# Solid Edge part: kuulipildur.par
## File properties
Author: Georg
Template: Iso Metric Part.par
Last saved by: Georg
Revision: 2
Application: Solid Edge
Accuracy: 0,990
Face Style: Model Default
Fill Style: Normal
Coef. of Thermal Exp: 0.0
Thermal Conductivity: 0.0
Specific Heat: 0.0
Modulus of Elasticity: 0.0
Poisson's Ratio: 0.0
Yield Stress: 0.0
Ultimate Stress: 0.0
Elongation: 0.0
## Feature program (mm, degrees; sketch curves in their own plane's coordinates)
sketch for "ExtrudedProtrusion_1" plane through (0, 4000, -150) normal (0, 0, 1) x-axis (1, 0, 0)
  circle centre (0, 420.2777) radius 100
extrude "ExtrudedProtrusion_1" add finite 20 along -normal
sketch for "ExtrudedProtrusion_6" plane through (0, 4350.2777, -620) normal (0, -1, 0) x-axis (1, 0, 0)
  circle centre (0, 0) radius 15
extrude "ExtrudedProtrusion_6" add finite 10 along +normal
sketch for "ExtrudedProtrusion_7" plane through (0, 4340.2777, -620) normal (0, -1, 0) x-axis (1, 0, 0)
  circle centre (0, 0) radius 100
extrude "ExtrudedProtrusion_7" add finite 20 along +normal
sketch for "ExtrudedProtrusion_8" plane through (0, 4320.2777, -620) normal (0, -1, 0) x-axis (1, 0, 0)
  circle centre (0, 59.2762) radius 30
extrude "ExtrudedProtrusion_8" add finite 520 along +normal
sketch for "ExtrudedProtrusion_9" #1 plane through (0, 3800.2777, -560.7238) normal (0, -1, 0) x-axis (1, 0, 0)
  circle centre (0, 0) radius 25
sketch for "ExtrudedProtrusion_9" #2 plane through (0, 3800.2777, -560.7238) normal (0, -1, 0) x-axis (1, 0, 0)
  circle centre (0, 0) radius 30
extrude "ExtrudedProtrusion_9" add finite 10 along +normal
sketch for "ExtrudedCutout_3" plane through (0, 3800.2777, -560.7238) normal (0, -1, 0) x-axis (1, 0, 0)
  circle centre (0, 0) radius 20
extrude "ExtrudedCutout_3" cut finite 510 along -normal
sketch for "ExtrudedCutout_4" #1 plane through (37.5, 4420.2777, -420) normal (-1, 0, 0) x-axis (0, 0, -1)
  circle centre (140.7238, 540) radius 12.5
sketch for "ExtrudedCutout_4" #2 plane through (37.5, 4420.2777, -420) normal (-1, 0, 0) x-axis (0, 0, -1)
  circle centre (140.7238, 480) radius 12.5
sketch for "ExtrudedCutout_4" #3 plane through (37.5, 4420.2777, -420) normal (-1, 0, 0) x-axis (0, 0, -1)
  circle centre (140.7238, 420) radius 12.5
sketch for "ExtrudedCutout_4" #4 plane through (37.5, 4420.2777, -420) normal (-1, 0, 0) x-axis (0, 0, -1)
  circle centre (140.7238, 365) radius 12.5
extrude "ExtrudedCutout_4" cut finite 35.7166 along +normal
pattern "Pattern_1" of "ExtrudedCutout_4" along a curve  XDirCount = 3; XDirSpacing = 41.8879 mm
extrude "unnamed Cutout 1" cut finite 35.7166
extrude "unnamed Cutout 2" cut finite 35.7166
pattern "Pattern_4" of "ExtrudedProtrusion_9", "Pattern_1", "ExtrudedCutout_3", "ExtrudedProtrusion_8" along a curve  XDirCount = 5; XDirSpacing = 125.6637 mm
extrude "unnamed Protrusion 1" add finite 520
extrude "unnamed Protrusion 2" add finite 10
extrude "unnamed Cutout 3" cut finite 510
extrude "unnamed Cutout 4" cut finite 35.7166
extrude "unnamed Cutout 5" cut finite 35.7166
extrude "unnamed Protrusion 3" add finite 520
extrude "unnamed Protrusion 4" add finite 10
extrude "unnamed Cutout 6" cut finite 510
extrude "unnamed Cutout 7" cut finite 35.7166
extrude "unnamed Cutout 8" cut finite 35.7166
extrude "unnamed Protrusion 5" add finite 520
extrude "unnamed Protrusion 6" add finite 10
extrude "unnamed Cutout 9" cut finite 510
extrude "unnamed Cutout 10" cut finite 35.7166
extrude "unnamed Cutout 11" cut finite 35.7166
extrude "unnamed Protrusion 7" add finite 520
extrude "unnamed Protrusion 8" add finite 10
extrude "unnamed Cutout 12" cut finite 510
extrude "unnamed Cutout 13" cut finite 35.7166
extrude "unnamed Cutout 14" cut finite 35.7166
sketch for "ExtrudedProtrusion_30" #1 plane through (0, 3820.2777, -620) normal (0, -1, 0) x-axis (1, 0, 0)
  circle centre (0, 0) radius 100
sketch for "ExtrudedProtrusion_30" #2 plane through (0, 3820.2777, -620) normal (0, -1, 0) x-axis (1, 0, 0)
  circle centre (56.375, 18.3174) radius 30
sketch for "ExtrudedProtrusion_30" #3 plane through (0, 3820.2777, -620) normal (0, -1, 0) x-axis (1, 0, 0)
  circle centre (34.8417, -47.9556) radius 30
sketch for "ExtrudedProtrusion_30" #4 plane through (0, 3820.2777, -620) normal (0, -1, 0) x-axis (1, 0, 0)
  circle centre (-34.8416, -47.9554) radius 30
sketch for "ExtrudedProtrusion_30" #5 plane through (0, 3820.2777, -620) normal (0, -1, 0) x-axis (1, 0, 0)
  circle centre (-56.375, 18.3174) radius 30
sketch for "ExtrudedProtrusion_30" #6 plane through (0, 3820.2777, -620) normal (0, -1, 0) x-axis (1, 0, 0)
  circle centre (0, 59.2762) radius 30
extrude "ExtrudedProtrusion_30" add finite 10 symmetric
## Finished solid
Body 1: solid body, 90 faces, 136 edges, 0 vertices, 2 separate solids.
  Faces by surface: cylinder 68, plane 22
  Edges by curve: intersection 88, circle 48
Bounding box of the edges (mm): 200.000 x 730.000 x 570.000, from (-100, 3790.2777, -720) to (100, 4520.2777, -150).
Cylindrical faces by radius (mm): R12.5 x44, R15 x1, R20 x5, R25 x5, R30 x10, R100 x3
Planar faces by outward normal: +y 3, +z 1, -y 17, -z 1
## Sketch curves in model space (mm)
line (0, 4273.694, -170) -> (-50, 4273.694, -170)
line (0, 4273.694, -170) -> (50, 4273.694, -170)
line (-37.5, 4370.2777, -170) -> (-62.5, 4370.2777, -170)
line (-62.5, 4370.2777, -170) -> (-62.5, 4470.2777, -170)
line (-62.5, 4470.2777, -170) -> (-37.5, 4470.2777, -170)
line (-37.5, 4470.2777, -170) -> (-37.5, 4370.2777, -170)
line (62.5, 4370.2777, -170) -> (37.5, 4370.2777, -170)
line (37.5, 4370.2777, -170) -> (37.5, 4470.2777, -170)
line (37.5, 4470.2777, -170) -> (62.5, 4470.2777, -170)
line (62.5, 4470.2777, -170) -> (62.5, 4370.2777, -170)
circle centre (0, 4420.2777, -150) radius 100
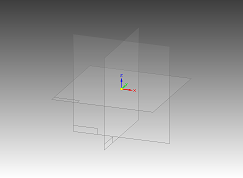
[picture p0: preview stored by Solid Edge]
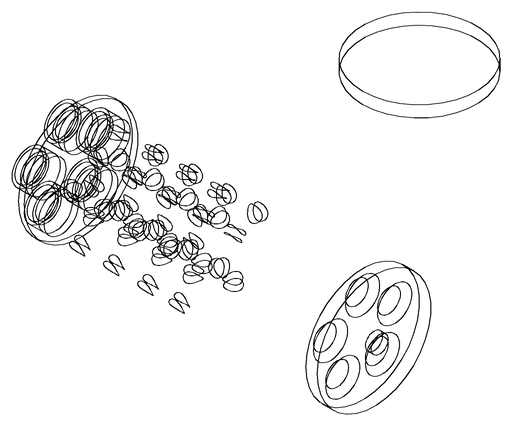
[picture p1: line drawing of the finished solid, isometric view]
